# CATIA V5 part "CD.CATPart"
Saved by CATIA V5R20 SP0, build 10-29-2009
Part number: CD
Material "Bleu clair DS": density 7860 kg/m3, Young's modulus 2e+11 Pa, Poisson ratio 0.266
Bounding box of the stored display mesh (mm): x 10.568 to 51.932, y -1.932 to 23.582, z -2 to 0
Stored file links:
  D:\IAO\22janv\CD.CATPart
  D:\IAO\22janv\czortea.CATProduct
  C:\Program Files\Dassault Systemes\B20\win_b64\startup\materials\French\Catalog.CATMaterial
  C:\Program Files\Dassault Systemes\B20\win_b64\startup\materials\blue_env_512x512.jpg
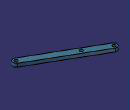
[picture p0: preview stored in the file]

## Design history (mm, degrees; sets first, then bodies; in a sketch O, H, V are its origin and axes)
External parameters (linked from other documents)
  External.epaisseur = 2 mm
Set1
  Plane1 "plan_ref": linked copy from another document
  Point1 "D": linked copy from another document
  Point2 "C": linked copy from another document
  Point3 "B": linked copy from another document
Body1 (main body), material "Bleu clair DS"
  Sketch1 on Plane1, origin (0, 0, 0), H (1, 0, 0), V (0, 1, 0)
    construction line L1 (12.5, 21.6506) -> (50, 0)
    point P1 (12.5, 21.6506)
    point P2 (50, 0)
    line L2 (13.5, 23.3827) -> (51, 1.7321)
    line L3 (49, -1.7321) -> (11.5, 19.9186)
    arc A1 centre (50, 0) radius 2 from (51, 1.7321) to (49, -1.7321) cw
    arc A2 centre (12.5, 21.6506) radius 2 from (11.5, 19.9186) to (13.5, 23.3827) cw
    reference projected point E1 (12.5, 21.6506) from Point1
    reference projected point E2 (50, 0) from Point2
    distance L1 L2 = 2 {= External.epaisseur}
    tangency: A1 L2, A2 L2, A1 L3, A2 L3
    coincidence: P1 E1, P2 E2
  Pad1: profile Sketch1, direction (0, 0, 1), length -2 {= -External.epaisseur}
  Sketch2 on start face of Pad1, origin (46.1629, 0.9223, 0), H (1, 0, 0), V (0, 1, 0)
    point P1 (3.8371, -0.9223)
    reference projected point E1 (3.8371, -0.9223) from Point2
    coincidence: P1 E1
  Hole1: placed by Sketch2, at (50, 0, 0) direction (0, 0, -1), diameter 2 {= External.epaisseur}, through (limit type 6)
  Sketch3 on start face of Pad1, origin (18.6762, 16.3587, 0), H (1, 0, 0), V (0, 1, 0)
    point P1 (-6.1762, 5.292)
    reference projected point E1 (-6.1762, 5.292) from Point1
    coincidence: P1 E1
  Hole2: placed by Sketch3, at (12.5, 21.6506, 0) direction (0, 0, -1), diameter 2 {= External.epaisseur}, through (limit type 6)
  Sketch4 on start face of Pad1, origin (35.3256, 6.7339, 0), H (1, 0, 0), V (0, 1, 0)
    point P1 (-10.3256, 7.6999)
    reference projected point E1 (-10.3256, 7.6999) from Point3
    coincidence: P1 E1
  Hole3: placed by Sketch4, at (25, 14.4338, 0) direction (0, 0, -1), diameter 2 {= External.epaisseur}, through (limit type 6)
